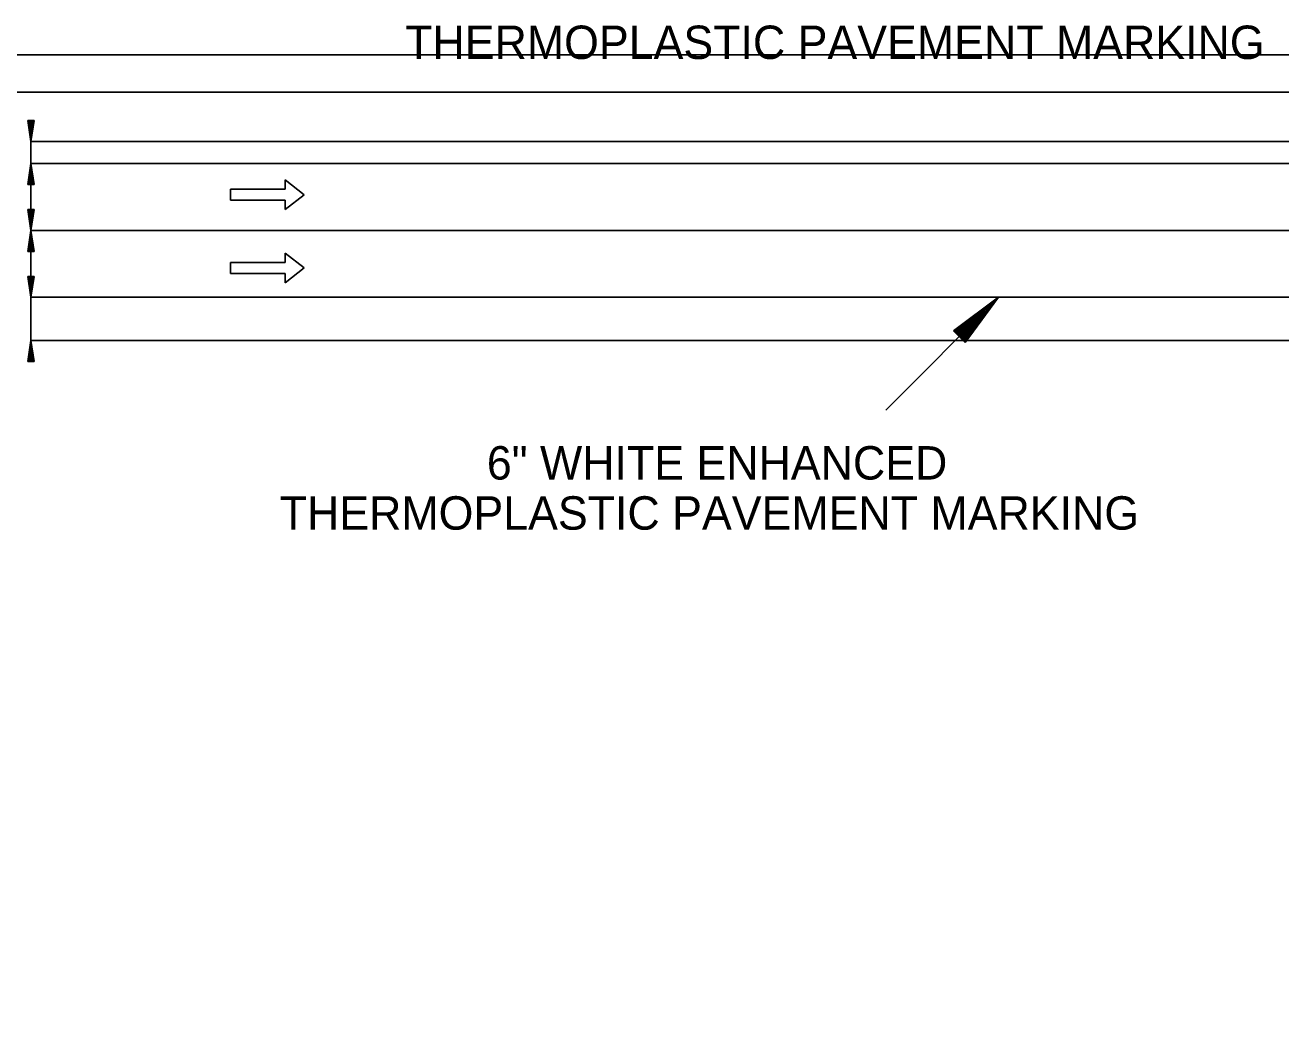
# Model space of a CAD drawing. Extents: x 1369895 to 1370228, y 380116 to 380329.
# Drawn here: x 1370011 to 1370078.6, y 380170.2 to 380224.2 of the extents above; entities that cross this region are included whole.
import ezdxf

# ---------------------------------------------------------------- set-up
doc = ezdxf.new("R2010")
doc.units = 0
for name, color, linetype in [('Default', 7, 'Continuous'), ('R_Border Plan-Plan', 7, 'Continuous'), ('R_Horz Alg', 7, 'Continuous'), ('R_MOT', 7, 'Continuous'), ('R_No Plot', 7, 'Continuous'), ('R_Proposed Road', 7, 'Continuous')]:
    doc.layers.add(name, color=color, linetype=linetype)

# ---------------------------------------------------------------- blocks, each defined once
blk = doc.blocks.new('SARROW')
at = {"layer": 'Default'}
for p, q in [((15.61, 8.23), (15.61, 3.23)), ((15.61, 8.23), (25.99, 0.23)), ((15.61, 3.23), (-13.81, 3.23)), ((-13.81, 3.23), (-13.81, -2.77)), ((25.99, 0.23), (15.61, -7.77)), ((15.61, -2.77), (-13.81, -2.77)), ((15.61, -2.77), (15.61, -7.77))]:
    blk.add_line(p, q, dxfattribs=at)

msp = doc.modelspace()

# ---------------------------------------------------------------- linework, layer by layer
at = {"layer": 'Default'}
for p, q in [((1370011.102, 380219.094), (1370011.27, 380217.969)), ((1370011.102, 380219.094), (1370011.439, 380219.094)), ((1370011.132, 380219.094), (1370011.27, 380218.157)), ((1370011.158, 380219.094), (1370011.27, 380218.352)), ((1370011.188, 380219.094), (1370011.27, 380218.54)), ((1370011.214, 380219.094), (1370011.27, 380218.731)), ((1370011.245, 380219.094), (1370011.27, 380218.919)), ((1370011.439, 380219.094), (1370011.27, 380217.969)), ((1370011.327, 380219.094), (1370011.27, 380218.731)), ((1370011.383, 380219.094), (1370011.27, 380218.352)), ((1370011.409, 380219.094), (1370011.27, 380218.157)), ((1370011.353, 380219.094), (1370011.27, 380218.54)), ((1370011.296, 380219.094), (1370011.27, 380218.919)), ((1370011.102, 380215.644), (1370011.27, 380216.769)), ((1370011.102, 380215.644), (1370011.27, 380216.769)), ((1370011.102, 380215.644), (1370011.27, 380216.769)), ((1370011.132, 380215.644), (1370011.27, 380216.581)), ((1370011.132, 380215.644), (1370011.27, 380216.581)), ((1370011.132, 380215.644), (1370011.27, 380216.581)), ((1370011.158, 380215.644), (1370011.27, 380216.387)), ((1370011.158, 380215.644), (1370011.27, 380216.387)), ((1370011.158, 380215.644), (1370011.27, 380216.387)), ((1370011.188, 380215.644), (1370011.27, 380216.199)), ((1370011.188, 380215.644), (1370011.27, 380216.199)), ((1370011.188, 380215.644), (1370011.27, 380216.199)), ((1370011.439, 380215.644), (1370011.27, 380216.769)), ((1370011.439, 380215.644), (1370011.27, 380216.769)), ((1370011.439, 380215.644), (1370011.27, 380216.769)), ((1370011.409, 380215.644), (1370011.27, 380216.581)), ((1370011.409, 380215.644), (1370011.27, 380216.581)), ((1370011.409, 380215.644), (1370011.27, 380216.581)), ((1370011.383, 380215.644), (1370011.27, 380216.387)), ((1370011.383, 380215.644), (1370011.27, 380216.387)), ((1370011.383, 380215.644), (1370011.27, 380216.387)), ((1370011.353, 380215.644), (1370011.27, 380216.199)), ((1370011.353, 380215.644), (1370011.27, 380216.199)), ((1370011.353, 380215.644), (1370011.27, 380216.199)), ((1370011.439, 380215.644), (1370011.102, 380215.644)), ((1370011.439, 380215.644), (1370011.102, 380215.644)), ((1370011.439, 380215.644), (1370011.102, 380215.644)), ((1370011.214, 380215.644), (1370011.27, 380216.008)), ((1370011.214, 380215.644), (1370011.27, 380216.008)), ((1370011.214, 380215.644), (1370011.27, 380216.008)), ((1370011.245, 380215.644), (1370011.27, 380215.82)), ((1370011.245, 380215.644), (1370011.27, 380215.82)), ((1370011.245, 380215.644), (1370011.27, 380215.82)), ((1370011.327, 380215.644), (1370011.27, 380216.008)), ((1370011.327, 380215.644), (1370011.27, 380216.008)), ((1370011.327, 380215.644), (1370011.27, 380216.008)), ((1370011.296, 380215.644), (1370011.27, 380215.82)), ((1370011.296, 380215.644), (1370011.27, 380215.82)), ((1370011.296, 380215.644), (1370011.27, 380215.82)), ((1370011.102, 380214.294), (1370011.27, 380213.169)), ((1370011.102, 380214.294), (1370011.439, 380214.294)), ((1370011.102, 380214.294), (1370011.27, 380213.169)), ((1370011.102, 380214.294), (1370011.439, 380214.294)), ((1370011.102, 380214.294), (1370011.27, 380213.169)), ((1370011.102, 380214.294), (1370011.439, 380214.294)), ((1370011.132, 380214.294), (1370011.27, 380213.357)), ((1370011.132, 380214.294), (1370011.27, 380213.357)), ((1370011.132, 380214.294), (1370011.27, 380213.357)), ((1370011.158, 380214.294), (1370011.27, 380213.552)), ((1370011.158, 380214.294), (1370011.27, 380213.552)), ((1370011.158, 380214.294), (1370011.27, 380213.552)), ((1370011.188, 380214.294), (1370011.27, 380213.74)), ((1370011.188, 380214.294), (1370011.27, 380213.74)), ((1370011.188, 380214.294), (1370011.27, 380213.74)), ((1370011.214, 380214.294), (1370011.27, 380213.931)), ((1370011.214, 380214.294), (1370011.27, 380213.931)), ((1370011.214, 380214.294), (1370011.27, 380213.931)), ((1370011.245, 380214.294), (1370011.27, 380214.119)), ((1370011.245, 380214.294), (1370011.27, 380214.119)), ((1370011.245, 380214.294), (1370011.27, 380214.119)), ((1370011.439, 380214.294), (1370011.27, 380213.169)), ((1370011.327, 380214.294), (1370011.27, 380213.931)), ((1370011.383, 380214.294), (1370011.27, 380213.552)), ((1370011.409, 380214.294), (1370011.27, 380213.357)), ((1370011.353, 380214.294), (1370011.27, 380213.74)), ((1370011.296, 380214.294), (1370011.27, 380214.119)), ((1370011.439, 380214.294), (1370011.27, 380213.169)), ((1370011.327, 380214.294), (1370011.27, 380213.931)), ((1370011.383, 380214.294), (1370011.27, 380213.552)), ((1370011.409, 380214.294), (1370011.27, 380213.357)), ((1370011.353, 380214.294), (1370011.27, 380213.74)), ((1370011.296, 380214.294), (1370011.27, 380214.119)), ((1370011.439, 380214.294), (1370011.27, 380213.169)), ((1370011.327, 380214.294), (1370011.27, 380213.931)), ((1370011.383, 380214.294), (1370011.27, 380213.552)), ((1370011.409, 380214.294), (1370011.27, 380213.357)), ((1370011.353, 380214.294), (1370011.27, 380213.74)), ((1370011.296, 380214.294), (1370011.27, 380214.119)), ((1370011.102, 380212.044), (1370011.27, 380213.169)), ((1370011.102, 380212.044), (1370011.27, 380213.169)), ((1370011.102, 380212.044), (1370011.27, 380213.169)), ((1370011.132, 380212.044), (1370011.27, 380212.981)), ((1370011.132, 380212.044), (1370011.27, 380212.981)), ((1370011.132, 380212.044), (1370011.27, 380212.981)), ((1370011.158, 380212.044), (1370011.27, 380212.787)), ((1370011.158, 380212.044), (1370011.27, 380212.787)), ((1370011.158, 380212.044), (1370011.27, 380212.787)), ((1370011.439, 380212.044), (1370011.27, 380213.169)), ((1370011.439, 380212.044), (1370011.27, 380213.169)), ((1370011.439, 380212.044), (1370011.27, 380213.169)), ((1370011.409, 380212.044), (1370011.27, 380212.981)), ((1370011.409, 380212.044), (1370011.27, 380212.981)), ((1370011.409, 380212.044), (1370011.27, 380212.981)), ((1370011.383, 380212.044), (1370011.27, 380212.787)), ((1370011.383, 380212.044), (1370011.27, 380212.787)), ((1370011.383, 380212.044), (1370011.27, 380212.787)), ((1370011.188, 380212.044), (1370011.27, 380212.599)), ((1370011.188, 380212.044), (1370011.27, 380212.599)), ((1370011.188, 380212.044), (1370011.27, 380212.599)), ((1370011.214, 380212.044), (1370011.27, 380212.408)), ((1370011.214, 380212.044), (1370011.27, 380212.408)), ((1370011.214, 380212.044), (1370011.27, 380212.408)), ((1370011.245, 380212.044), (1370011.27, 380212.22)), ((1370011.245, 380212.044), (1370011.27, 380212.22)), ((1370011.245, 380212.044), (1370011.27, 380212.22)), ((1370011.353, 380212.044), (1370011.27, 380212.599)), ((1370011.353, 380212.044), (1370011.27, 380212.599)), ((1370011.353, 380212.044), (1370011.27, 380212.599)), ((1370011.327, 380212.044), (1370011.27, 380212.408)), ((1370011.327, 380212.044), (1370011.27, 380212.408)), ((1370011.327, 380212.044), (1370011.27, 380212.408)), ((1370011.296, 380212.044), (1370011.27, 380212.22)), ((1370011.296, 380212.044), (1370011.27, 380212.22)), ((1370011.296, 380212.044), (1370011.27, 380212.22)), ((1370011.439, 380212.044), (1370011.102, 380212.044)), ((1370011.439, 380212.044), (1370011.102, 380212.044)), ((1370011.439, 380212.044), (1370011.102, 380212.044)), ((1370011.102, 380210.694), (1370011.27, 380209.569)), ((1370011.102, 380210.694), (1370011.439, 380210.694)), ((1370011.102, 380210.694), (1370011.27, 380209.569)), ((1370011.102, 380210.694), (1370011.439, 380210.694)), ((1370011.102, 380210.694), (1370011.27, 380209.569)), ((1370011.102, 380210.694), (1370011.439, 380210.694)), ((1370011.132, 380210.694), (1370011.27, 380209.757)), ((1370011.132, 380210.694), (1370011.27, 380209.757)), ((1370011.132, 380210.694), (1370011.27, 380209.757)), ((1370011.158, 380210.694), (1370011.27, 380209.952)), ((1370011.158, 380210.694), (1370011.27, 380209.952)), ((1370011.158, 380210.694), (1370011.27, 380209.952)), ((1370011.188, 380210.694), (1370011.27, 380210.14)), ((1370011.188, 380210.694), (1370011.27, 380210.14)), ((1370011.188, 380210.694), (1370011.27, 380210.14)), ((1370011.214, 380210.694), (1370011.27, 380210.331)), ((1370011.214, 380210.694), (1370011.27, 380210.331)), ((1370011.214, 380210.694), (1370011.27, 380210.331)), ((1370011.245, 380210.694), (1370011.27, 380210.519)), ((1370011.245, 380210.694), (1370011.27, 380210.519)), ((1370011.245, 380210.694), (1370011.27, 380210.519)), ((1370011.439, 380210.694), (1370011.27, 380209.569)), ((1370011.327, 380210.694), (1370011.27, 380210.331)), ((1370011.383, 380210.694), (1370011.27, 380209.952)), ((1370011.409, 380210.694), (1370011.27, 380209.757)), ((1370011.353, 380210.694), (1370011.27, 380210.14)), ((1370011.296, 380210.694), (1370011.27, 380210.519)), ((1370011.439, 380210.694), (1370011.27, 380209.569)), ((1370011.327, 380210.694), (1370011.27, 380210.331)), ((1370011.383, 380210.694), (1370011.27, 380209.952)), ((1370011.409, 380210.694), (1370011.27, 380209.757)), ((1370011.353, 380210.694), (1370011.27, 380210.14)), ((1370011.296, 380210.694), (1370011.27, 380210.519)), ((1370011.439, 380210.694), (1370011.27, 380209.569)), ((1370011.327, 380210.694), (1370011.27, 380210.331)), ((1370011.383, 380210.694), (1370011.27, 380209.952)), ((1370011.409, 380210.694), (1370011.27, 380209.757)), ((1370011.353, 380210.694), (1370011.27, 380210.14)), ((1370011.296, 380210.694), (1370011.27, 380210.519)), ((1370060.935, 380207.766), (1370063.375, 380209.569)), ((1370060.935, 380207.766), (1370063.375, 380209.569)), ((1370060.935, 380207.766), (1370063.375, 380209.569)), ((1370061.571, 380207.13), (1370063.375, 380209.569)), ((1370061.571, 380207.13), (1370063.375, 380209.569)), ((1370061.571, 380207.13), (1370063.375, 380209.569)), ((1370060.992, 380207.709), (1370063.02, 380209.215)), ((1370060.992, 380207.709), (1370063.02, 380209.215)), ((1370060.992, 380207.709), (1370063.02, 380209.215)), ((1370061.041, 380207.66), (1370062.653, 380208.848)), ((1370061.041, 380207.66), (1370062.653, 380208.848)), ((1370061.041, 380207.66), (1370062.653, 380208.848)), ((1370061.465, 380207.236), (1370062.653, 380208.848)), ((1370061.465, 380207.236), (1370062.653, 380208.848)), ((1370061.465, 380207.236), (1370062.653, 380208.848)), ((1370061.514, 380207.187), (1370063.02, 380209.215)), ((1370061.514, 380207.187), (1370063.02, 380209.215)), ((1370061.514, 380207.187), (1370063.02, 380209.215)), ((1370061.098, 380207.603), (1370062.299, 380208.494)), ((1370061.098, 380207.603), (1370062.299, 380208.494)), ((1370061.098, 380207.603), (1370062.299, 380208.494)), ((1370061.147, 380207.554), (1370061.938, 380208.133)), ((1370061.147, 380207.554), (1370061.938, 380208.133)), ((1370061.147, 380207.554), (1370061.938, 380208.133)), ((1370061.359, 380207.342), (1370061.938, 380208.133)), ((1370061.359, 380207.342), (1370061.938, 380208.133)), ((1370061.359, 380207.342), (1370061.938, 380208.133)), ((1370061.408, 380207.293), (1370062.299, 380208.494)), ((1370061.408, 380207.293), (1370062.299, 380208.494)), ((1370061.408, 380207.293), (1370062.299, 380208.494)), ((1370061.571, 380207.13), (1370060.935, 380207.766)), ((1370061.571, 380207.13), (1370060.935, 380207.766)), ((1370061.571, 380207.13), (1370060.935, 380207.766)), ((1370061.204, 380207.497), (1370061.584, 380207.779)), ((1370061.204, 380207.497), (1370061.584, 380207.779)), ((1370061.204, 380207.497), (1370061.584, 380207.779)), ((1370061.302, 380207.399), (1370061.584, 380207.779)), ((1370061.302, 380207.399), (1370061.584, 380207.779)), ((1370061.302, 380207.399), (1370061.584, 380207.779)), ((1370011.102, 380206.119), (1370011.27, 380207.244)), ((1370011.132, 380206.119), (1370011.27, 380207.056)), ((1370011.158, 380206.119), (1370011.27, 380206.862)), ((1370011.188, 380206.119), (1370011.27, 380206.674)), ((1370011.439, 380206.119), (1370011.27, 380207.244)), ((1370011.409, 380206.119), (1370011.27, 380207.056)), ((1370011.383, 380206.119), (1370011.27, 380206.862)), ((1370011.353, 380206.119), (1370011.27, 380206.674)), ((1370011.439, 380206.119), (1370011.102, 380206.119)), ((1370011.214, 380206.119), (1370011.27, 380206.483)), ((1370011.245, 380206.119), (1370011.27, 380206.295)), ((1370011.327, 380206.119), (1370011.27, 380206.483)), ((1370011.296, 380206.119), (1370011.27, 380206.295))]:
    msp.add_line(p, q, dxfattribs=at)
at = {"layer": 'R_Border Plan-Plan'}
msp.add_line((1369907.122, 380222.622), (1370223.302, 380222.622), dxfattribs=at)
at = {"layer": 'R_Horz Alg'}
msp.add_line((1370011.27, 380213.169), (1370116.27, 380213.169), dxfattribs=at)
at = {"layer": 'R_No Plot'}
msp.add_lwpolyline([(1369909.122, 380220.622), (1370221.302, 380220.622), (1370221.302, 380121.892), (1369909.122, 380121.892)], close=True, dxfattribs=at)
at = {"layer": 'R_Proposed Road'}
for p, q in [((1370011.27, 380217.969), (1370011.27, 380216.769)), ((1370011.27, 380217.969), (1370116.27, 380217.969)), ((1370011.27, 380216.769), (1370011.27, 380213.169)), ((1370011.27, 380216.769), (1370116.27, 380216.769)), ((1370011.27, 380216.769), (1370011.27, 380213.169)), ((1370011.27, 380216.769), (1370011.27, 380213.169)), ((1370011.27, 380213.169), (1370011.27, 380209.569)), ((1370011.27, 380213.169), (1370011.27, 380209.569)), ((1370011.27, 380213.169), (1370011.27, 380209.569)), ((1370011.27, 380209.569), (1370116.27, 380209.569)), ((1370011.27, 380209.569), (1370011.27, 380207.244)), ((1370057.291, 380203.486), (1370063.375, 380209.569)), ((1370057.291, 380203.486), (1370063.375, 380209.569)), ((1370057.291, 380203.486), (1370063.375, 380209.569)), ((1370011.27, 380207.244), (1370116.27, 380207.244))]:
    msp.add_line(p, q, dxfattribs=at)

# ---------------------------------------------------------------- block references
at = {"layer": 'R_MOT', "xscale": 0.09999996, "yscale": 0.09999996, "rotation": 9.398539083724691e-12}
for p in [(1370023.389, 380215.073), (1370023.389, 380211.127)]:
    msp.add_blockref('SARROW', p, dxfattribs=at)

# ---------------------------------------------------------------- texts
at = {"layer": 'Default'}
for s, p in [('THERMOPLASTIC PAVEMENT MARKING', (1370031.419, 380222.404)), ('6" WHITE ENHANCED ', (1370035.817, 380199.754)), ('THERMOPLASTIC PAVEMENT MARKING', (1370024.663, 380197.054))]:
    msp.add_text(s, height=1.8, dxfattribs=at).set_placement(p)

doc.saveas('drawing.dxf')
